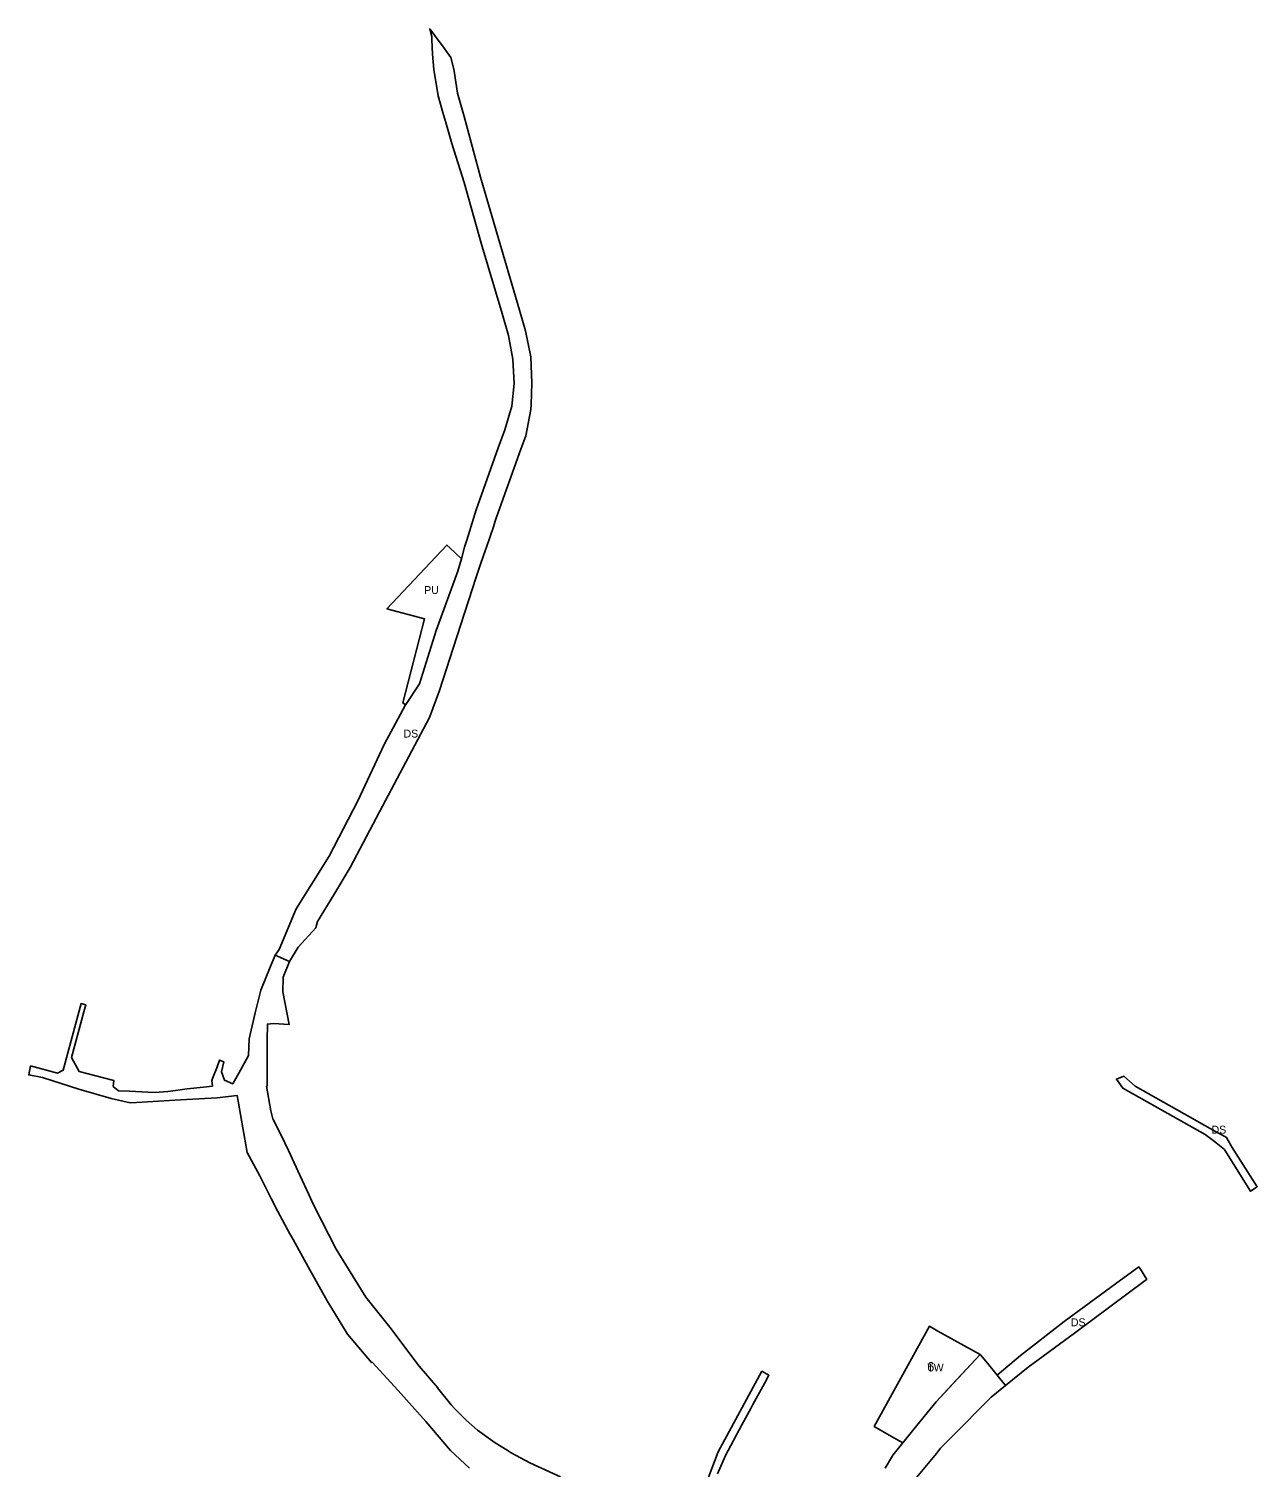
# Model space of a CAD drawing. Extents: x -540396 to -537847, y -1162344 to -1159959.
# Drawn here: x -538624 to -537847, y -1161270 to -1160359 of the extents above; entities that cross this region are included whole.
import ezdxf

# ---------------------------------------------------------------- set-up
doc = ezdxf.new("R2010")
doc.units = 0
for name, color, linetype in [('90320013', 7, 'Continuous'), ('90390023', 7, 'Continuous'), ('90450013', 7, 'Continuous'), ('ID_navrh', 7, 'Continuous')]:
    doc.layers.add(name, color=color, linetype=linetype)

msp = doc.modelspace()

# ---------------------------------------------------------------- linework, layer by layer
at = {"layer": '90320013'}
for points in [[(-538355.32, -1160384.48), (-538355.12, -1160385.74), (-538352.88, -1160399.7), (-538348.84, -1160414.57), (-538338.41, -1160452.93), (-538327.23, -1160491.04), (-538315.19, -1160532.1), (-538309.86, -1160550.28), (-538306.54, -1160566.65), (-538305.82, -1160583.33), (-538306.26, -1160596.82), (-538306.6, -1160600.01), (-538309.68, -1160616.62), (-538312.77, -1160625.25), (-538328.18, -1160668.31), (-538329.28, -1160671.49), (-538330.23, -1160674.25), (-538334.69, -1160687.17), (-538336.54, -1160692.52), (-538336.76, -1160693.14), (-538338.41, -1160697.91), (-538341.15, -1160706.33), (-538353.36, -1160743.92), (-538364.45, -1160778.07), (-538370.7, -1160795.06), (-538402.43, -1160854.81), (-538420.84, -1160890.16), (-538431.35, -1160907.37), (-538441.72, -1160924.35), (-538442.66, -1160928.28), (-538453.78, -1160940.64), (-538459.28, -1160949.68), (-538468.45, -1160945.63), (-538465.91, -1160942.01), (-538455.22, -1160916.24), (-538434.13, -1160882.98), (-538416.18, -1160847.88), (-538399.17, -1160811.69), (-538392.23, -1160798.92), (-538385.81, -1160787.12), (-538385.67, -1160786.86), (-538376.95, -1160773.81), (-538366.57, -1160739.98), (-538352.68, -1160702.53), (-538350.5, -1160694.55), (-538348.53, -1160687.31), (-538347.11, -1160682.71), (-538341.19, -1160663.56), (-538327.17, -1160624.4), (-538323.05, -1160612.86), (-538318.62, -1160597.9), (-538317.03, -1160583.49), (-538317.93, -1160568.07), (-538320.65, -1160553.21), (-538324.7, -1160539.29), (-538337.94, -1160494.81), (-538348.78, -1160456.25), (-538356.56, -1160431.65), (-538360.43, -1160418.26), (-538362.23, -1160412.05), (-538365.12, -1160401.34), (-538367.88, -1160384.77), (-538368.74, -1160375.12), (-538369.19, -1160365.99), (-538369.3, -1160363.86), (-538370.49, -1160358.94), (-538366.89, -1160363.81), (-538361.36, -1160371.31), (-538357.11, -1160377.08)], [(-537862.75, -1161066.81), (-537846.51, -1161092.3), (-537850.7, -1161095.11), (-537867, -1161069.02), (-537867.27, -1161068.59), (-537872.42, -1161064.54), (-537872.72, -1161064.31), (-537879.46, -1161059.19), (-537931.57, -1161029.91), (-537931.57, -1161029.91), (-537935.72, -1161024.07), (-537931.08, -1161022.13), (-537923.87, -1161028.46), (-537923.87, -1161028.46), (-537871.46, -1161058.02), (-537866.26, -1161060.95), (-537865.95, -1161061.12), (-537863.04, -1161066.36)], [(-538011.287, -1161211.511), (-537996.47, -1161199.19), (-537968.86, -1161177.68), (-537936.28, -1161153.8), (-537921.55, -1161143.01), (-537920.43, -1161144.55), (-537916.45, -1161150.91), (-537917.43, -1161151.64), (-537962.32, -1161184.95), (-537991.61, -1161206.61), (-538005.902, -1161218.169), (-538005.902, -1161218.169)]]:
    msp.add_lwpolyline(points, close=True, dxfattribs=at)
at = {"layer": '90390023'}
msp.add_lwpolyline([(-538063.936, -1161245.866), (-538070.89, -1161254.46), (-538078.07, -1161250.34), (-538088.992, -1161244.066), (-538054.155, -1161180.606), (-538048.69, -1161183.64), (-538021.99, -1161198.46), (-538049.86, -1161228.47)], close=True, dxfattribs=at)
at = {"layer": '90450013'}
msp.add_lwpolyline([(-538357.79, -1160687.71), (-538350.5, -1160694.55), (-538352.68, -1160702.53), (-538366.57, -1160739.98), (-538376.95, -1160773.81), (-538385.67, -1160786.86), (-538385.81, -1160787.12), (-538387.55, -1160785.84), (-538373.88, -1160732.56), (-538397.64, -1160726.21), (-538359.69, -1160685.93)], close=True, dxfattribs=at)
for points in [[(-538345.34, -1161270.42), (-538357.37, -1161259.2), (-538373.1, -1161240.95), (-538390.5, -1161221.38), (-538407.04, -1161203.36), (-538407.38, -1161203.61), (-538422.64, -1161185.64), (-538435.52, -1161164.53), (-538447.63, -1161142.88), (-538457.08, -1161125.62), (-538459.07, -1161122.1), (-538466.64, -1161107.89), (-538471, -1161099.7), (-538478.18, -1161085.45), (-538480.58, -1161080.62), (-538482.08, -1161077.92), (-538486.14, -1161070.57), (-538492.59, -1161034.4), (-538505.25, -1161036.01), (-538528.46, -1161037.29), (-538556.33, -1161038.83), (-538560.34, -1161039.05), (-538572.22, -1161036.31), (-538592.8, -1161030.52), (-538615.86, -1161023.09), (-538624.464, -1161021.399), (-538624.464, -1161021.399), (-538623.346, -1161015.71), (-538606.25, -1161020.36), (-538602.59, -1161018.44), (-538591.31, -1160976.212), (-538588.385, -1160976.999), (-538589.59, -1160981.48), (-538593.18, -1160994.8), (-538597.35, -1161010.43), (-538592.52, -1161019.28), (-538570.51, -1161025.06), (-538571.12, -1161028.69), (-538567.63, -1161031.44), (-538560.58, -1161031.8), (-538549.04, -1161032.43), (-538544.35, -1161032.65), (-538541.82, -1161032.4), (-538536.45, -1161031.87), (-538531.49, -1161031.26), (-538524.1, -1161030.31), (-538513.73, -1161029.1), (-538510.02, -1161028.7), (-538508.21, -1161028.49), (-538508.5, -1161024.95), (-538508.04, -1161023.77), (-538505.46, -1161016.85), (-538503.58, -1161012), (-538501.02, -1161013.1), (-538502.33, -1161019.47), (-538500.45, -1161024.84), (-538495.29, -1161027.13), (-538490.41, -1161018.35), (-538485.39, -1161009.2), (-538484.89, -1160998.68), (-538481, -1160982.21), (-538477.46, -1160967.7), (-538471.55, -1160953.26), (-538468.45, -1160945.63), (-538459.28, -1160949.68), (-538463.26, -1160959.5), (-538463.52, -1160968.91), (-538459.56, -1160989.48), (-538469.43, -1160988.9), (-538473.37, -1160989.24), (-538473.41, -1160999.72), (-538473.52, -1161017.94), (-538473.54, -1161028.5), (-538473.98, -1161028.57), (-538471.24, -1161044.12), (-538469.88, -1161049.16), (-538468.05, -1161052.84), (-538462.33, -1161064.36), (-538460.08, -1161069.26), (-538452.9, -1161084.89), (-538447.04, -1161097.23), (-538444.25, -1161103.76), (-538429.82, -1161131.69), (-538421.99, -1161144.47), (-538411, -1161162.23), (-538395.91, -1161181.26), (-538377.3, -1161205.85), (-538365.38, -1161219.5), (-538365.6, -1161219.68), (-538357.04, -1161230.35), (-538354.59, -1161232.82), (-538347.45, -1161240.04), (-538340.37, -1161246.31), (-538329.07, -1161254.35), (-538321.56, -1161259.09), (-538320.28, -1161259.82), (-538318.89, -1161260.73), (-538307.21, -1161266.99), (-538302.11, -1161269.38), (-538287.76, -1161276)], [(-538082.21, -1161270.41), (-538077.49, -1161262.62), (-538077.18, -1161262.24), (-538070.89, -1161254.46), (-538063.936, -1161245.866), (-538049.86, -1161228.47), (-538045.026, -1161223.265), (-538045.026, -1161223.265), (-538042.667, -1161220.724), (-538021.99, -1161198.46), (-538021.73, -1161198.6), (-538017.371, -1161203.989), (-538011.287, -1161211.511), (-538011.287, -1161211.511), (-538005.902, -1161218.169), (-538005.902, -1161218.169), (-538014.94, -1161225.48), (-538040.75, -1161251.55), (-538047.04, -1161257.9), (-538049.68, -1161261.08), (-538064.4, -1161278.84)], [(-538196.6, -1161282.98), (-538187.83, -1161260.14), (-538160.18, -1161209.13), (-538155.716, -1161211.579), (-538158.58, -1161216.8), (-538158.58, -1161216.8), (-538165.84, -1161230.16), (-538167.26, -1161232.77), (-538172.84, -1161243.04), (-538183.26, -1161262.48), (-538188.28, -1161273.97)]]:
    msp.add_lwpolyline(points, dxfattribs=at)

# ---------------------------------------------------------------- texts
at = {"layer": '90320013'}
for rotation, p in [(360, (-538387.135, -1160807.782)), (0, (-537875.435, -1161058.62)), (360, (-537964.519, -1161180.59))]:
    msp.add_text('DS', height=5, rotation=rotation, dxfattribs=at).set_placement(p)
at = {"layer": '90390023'}
msp.add_text('TW', height=5, rotation=360, dxfattribs=at).set_placement((-538055.491, -1161209.234))
at = {"layer": '90450013'}
msp.add_text('PU', height=5, rotation=360, dxfattribs=at).set_placement((-538374.07, -1160716.851))
at = {"layer": 'ID_navrh'}
msp.add_text('6', height=6, rotation=0, dxfattribs=at).set_placement((-538055.491, -1161209.234))

doc.saveas('drawing.dxf')
